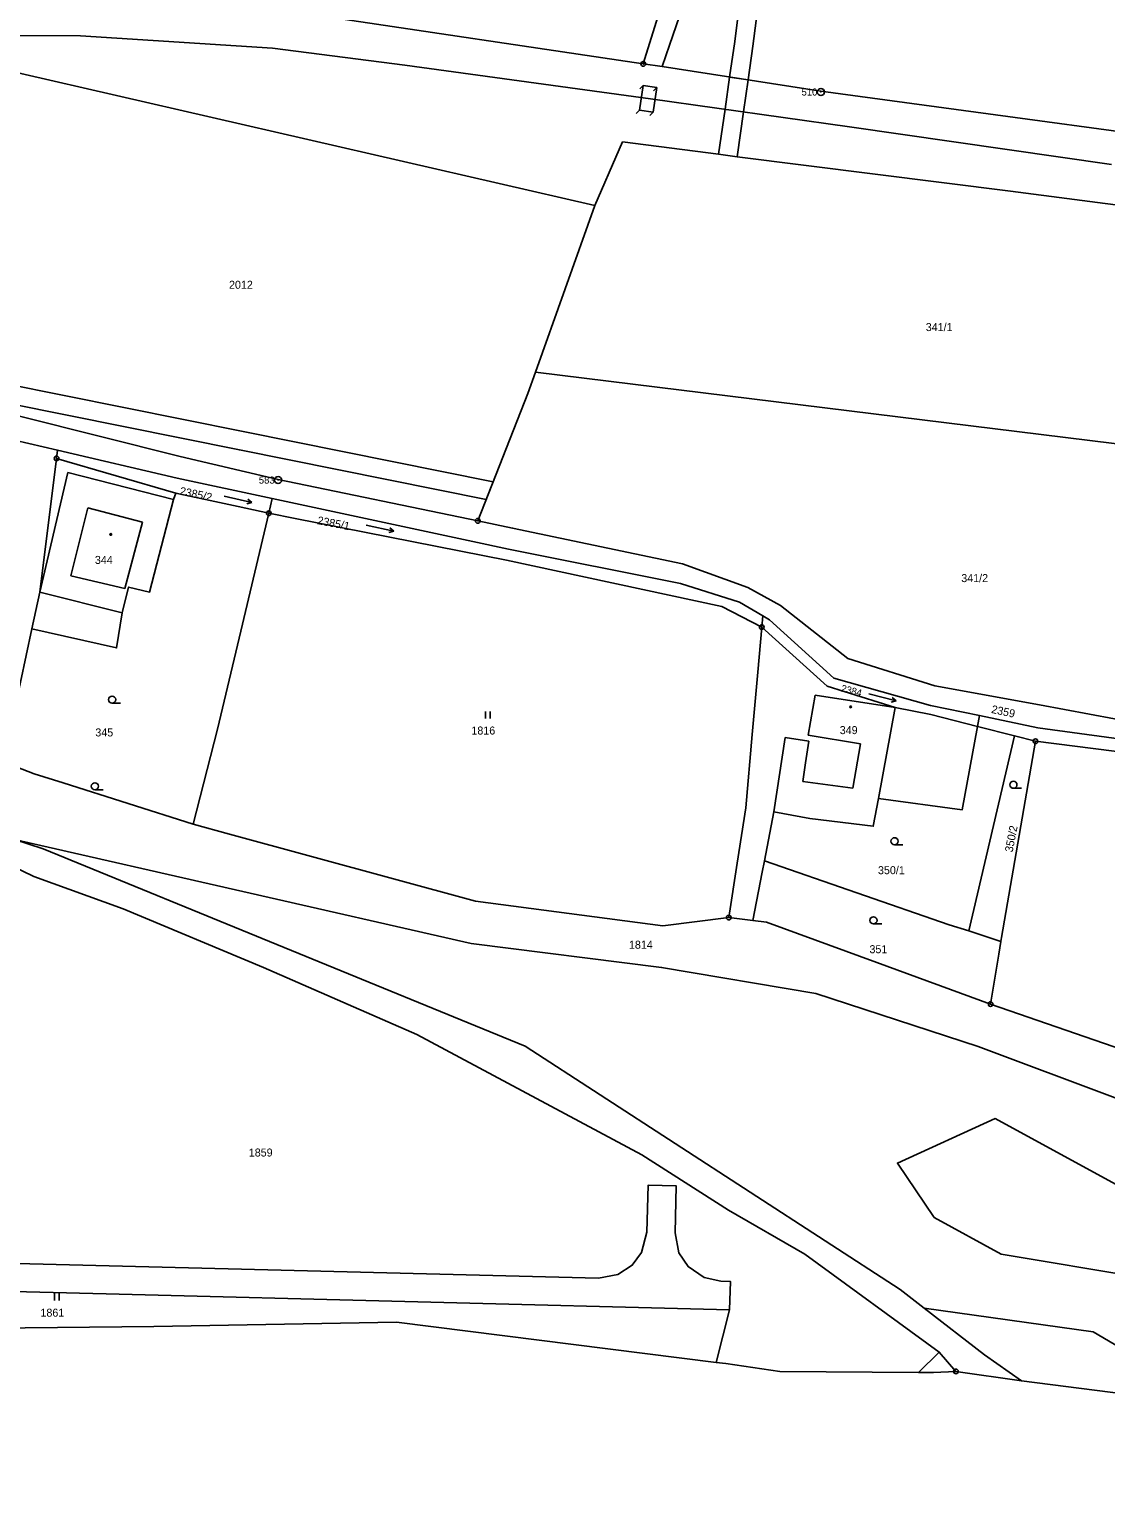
# Model space of a CAD drawing. Extents: x -504988 to -494607, y -1123820 to -1114018.
# Drawn here: x -500871.3 to -500642.7, y -1121663.8 to -1121354.5 of the extents above; entities that cross this region are included whole.
import ezdxf

# ---------------------------------------------------------------- set-up
doc = ezdxf.new("R2010")
doc.units = 0
for name, color, linetype in [('Hranice parcel', 7, 'Continuous'), ('Parcelní čísla', 7, 'Continuous'), ('Polygon ku', 7, 'Continuous'), ('Poz předměty', 7, 'Continuous'), ('Vnitřní kresba', 7, 'Continuous'), ('Věcná břemena k části', 7, 'Continuous'), ('Značky bodu BP', 7, 'Continuous'), ('Značky budov', 7, 'Continuous'), ('Značky kultur', 7, 'Continuous')]:
    doc.layers.add(name, color=color, linetype=linetype)

msp = doc.modelspace()

# ---------------------------------------------------------------- linework, layer by layer
at = {"layer": 'Hranice parcel'}
for p, q in [((-500736.95, -1121362.41), (-500740.93, -1121361.85)), ((-500592.37, -1121398.1), (-500662.99, -1121388.88)), ((-500751.26, -1121391.94), (-500763.83, -1121427.34)), ((-500763.83, -1121427.34), (-500626.53, -1121444.24)), ((-500874.41, -1121441.77), (-500865.27, -1121443.9)), ((-500865.49, -1121445.64), (-500865.27, -1121443.9)), ((-500840.16, -1121452.97), (-500865.49, -1121445.64)), ((-500819.71, -1121454.13), (-500820.45, -1121457.26)), ((-500715.59, -1121479.05), (-500715.8, -1121481.45)), ((-500669.56, -1121500.25), (-500669.98, -1121502.56)), ((-500671.79, -1121545.93), (-500662.11, -1121504.57)), ((-500669.98, -1121502.56), (-500662.11, -1121504.57)), ((-500662.11, -1121504.57), (-500657.68, -1121505.7)), ((-500722.8, -1121543.13), (-500717.66, -1121543.78)), ((-500671.79, -1121545.93), (-500665.04, -1121548.2)), ((-500722.6, -1121626.43), (-500725.45, -1121637.62)), ((-500711.93, -1121639.55), (-500682.48, -1121639.75)), ((-500682.48, -1121639.75), (-500679.35, -1121639.77))]:
    msp.add_line(p, q, dxfattribs=at)
for points in [[(-500690.57, -1121193.22), (-500703.36, -1121227.53), (-500712.38, -1121256.12), (-500723.06, -1121305.36), (-500727.01, -1121333.6), (-500735.38, -1121357.86), (-500736.95, -1121362.41)], [(-500725.11, -1121294.84), (-500727.31, -1121304.65), (-500731.94, -1121332.69), (-500740.93, -1121361.85)], [(-500740.93, -1121361.85), (-500811.39, -1121351.34), (-500852.46, -1121350.08)], [(-500751.26, -1121391.94), (-500873.05, -1121363.84), (-500902.25, -1121362.4), (-500923.9, -1121363.52)], [(-500736.95, -1121362.41), (-500703.27, -1121367.64), (-500597.75, -1121381.92), (-500477.19, -1121398.11), (-500356.62, -1121414.3), (-500315.76, -1121422.98), (-500161.41, -1121474.74), (-500042.51, -1121512.37), (-499891.6, -1121561.19), (-499861.16, -1121571.4), (-499858.09, -1121572.43), (-499855.23, -1121568.88), (-499853.4, -1121569.81), (-499853.07, -1121569.98)], [(-500745.37, -1121378.41), (-500746.07, -1121380.02), (-500751.26, -1121391.94)], [(-500662.99, -1121388.88), (-500720.99, -1121381.55), (-500724.95, -1121380.99), (-500745.37, -1121378.41)], [(-500900.02, -1121427.3), (-500892.26, -1121430.03), (-500873.35, -1121436.67), (-500839.28, -1121445.2), (-500818.48, -1121450.11), (-500776.09, -1121458.88)], [(-500763.83, -1121427.34), (-500765.42, -1121431.83), (-500776.09, -1121458.88)], [(-500865.49, -1121445.64), (-500869.08, -1121474.01), (-500870.74, -1121481.82)], [(-500865.27, -1121443.9), (-500839.89, -1121449.8), (-500819.71, -1121454.13)], [(-500870.74, -1121481.82), (-500852.77, -1121485.86), (-500851.59, -1121478.44), (-500850.2, -1121472.96), (-500845.76, -1121474.01), (-500840.68, -1121454.34), (-500840.16, -1121452.97)], [(-500820.45, -1121457.26), (-500826.92, -1121455.85), (-500840.16, -1121452.97)], [(-500819.71, -1121454.13), (-500777.12, -1121463.27), (-500769.52, -1121464.9), (-500733.07, -1121472.16), (-500720.52, -1121476.15), (-500715.59, -1121479.05)], [(-500836.53, -1121523.32), (-500831.3, -1121503.14), (-500826.38, -1121482.32), (-500825.39, -1121478.13), (-500820.45, -1121457.26)], [(-500715.8, -1121481.45), (-500724.29, -1121477.11), (-500769.95, -1121467.26), (-500814.87, -1121458.36), (-500820.45, -1121457.26)], [(-500776.09, -1121458.88), (-500768.67, -1121460.41), (-500732.61, -1121467.98), (-500718.71, -1121473.02), (-500711.84, -1121476.83), (-500697.53, -1121488.14), (-500679.07, -1121493.94), (-500656.85, -1121497.97), (-500640.87, -1121500.9), (-500631.84, -1121501.01)], [(-500715.59, -1121479.05), (-500714.16, -1121479.89), (-500700.47, -1121492.27), (-500679.94, -1121498.09), (-500669.56, -1121500.25)], [(-500870.74, -1121481.82), (-500875.55, -1121504.45), (-500875.85, -1121508.37), (-500874.09, -1121511.1)], [(-500715.8, -1121481.45), (-500716.64, -1121491.01), (-500717.47, -1121500.37), (-500717.81, -1121504.23), (-500719.18, -1121519.81), (-500721.01, -1121531.58), (-500722.8, -1121543.13)], [(-500669.98, -1121502.56), (-500679.9, -1121500.03), (-500687.45, -1121498.52), (-500701.88, -1121494.02), (-500715.8, -1121481.45)], [(-500585.55, -1121517.36), (-500587.8, -1121513.67), (-500607.61, -1121508.47), (-500617.46, -1121506.84), (-500627.25, -1121505.73), (-500641.03, -1121505.04), (-500657.2, -1121502.82), (-500669.56, -1121500.25)], [(-500669.98, -1121502.56), (-500673.24, -1121520.29), (-500691.02, -1121517.85), (-500692.11, -1121523.75), (-500705.55, -1121522.1), (-500713.24, -1121520.67), (-500715.23, -1121531.09)], [(-500657.68, -1121505.7), (-500664.89, -1121547.36), (-500665.04, -1121548.2)], [(-500585.55, -1121517.36), (-500617.74, -1121510.38), (-500627.3, -1121508.95), (-500641, -1121507.8), (-500657.68, -1121505.7)], [(-500874.09, -1121511.1), (-500870.23, -1121512.61), (-500864.09, -1121514.56), (-500836.53, -1121523.32)], [(-500722.8, -1121543.13), (-500736.77, -1121544.89), (-500776.55, -1121539.63), (-500828.81, -1121525.42), (-500836.53, -1121523.32)], [(-500874.41, -1121526.57), (-500777.49, -1121548.63), (-500737.05, -1121553.73), (-500704.29, -1121559.25), (-500669.82, -1121570.54), (-500611.11, -1121592.54), (-500572.54, -1121605.34), (-500559.62, -1121606.59), (-500553.26, -1121605.17), (-500533.2, -1121604.53), (-500509.38, -1121604.76), (-500480.9, -1121603.04), (-500474.44, -1121603.7)], [(-500874.41, -1121526.57), (-500868.34, -1121528.51), (-500766.02, -1121570.45), (-500686.39, -1121622.16), (-500681.34, -1121626.07)], [(-500682.48, -1121639.75), (-500678.12, -1121635.45), (-500706.61, -1121614.66), (-500722.83, -1121605.3), (-500741.28, -1121593.54), (-500789.04, -1121568.01), (-500821.54, -1121553.77), (-500851.38, -1121541.32), (-500870.35, -1121534.44), (-500875.3, -1121532), (-500878.74, -1121531.16), (-500880.51, -1121532.35)], [(-500717.66, -1121543.78), (-500715.7, -1121533.48), (-500715.23, -1121531.09)], [(-500715.23, -1121531.09), (-500676.01, -1121544.69), (-500671.79, -1121545.93)], [(-500667.21, -1121561.51), (-500691.35, -1121552.65), (-500714.77, -1121544.15), (-500717.66, -1121543.78)], [(-500665.04, -1121548.2), (-500665.48, -1121550.9), (-500667.21, -1121561.51)], [(-500472.98, -1121588.34), (-500480.26, -1121592.21), (-500492.56, -1121594.8), (-500533.66, -1121596.03), (-500553.37, -1121596.25), (-500571.08, -1121594.77), (-500667.21, -1121561.51)], [(-500681.34, -1121626.07), (-500645.4, -1121631.11), (-500627.77, -1121641.56), (-500600.14, -1121648.61), (-500575.22, -1121652.3), (-500635.34, -1121619.61), (-500664.97, -1121614.6), (-500679.19, -1121606.84), (-500686.99, -1121595.27), (-500666.26, -1121585.83), (-500573.75, -1121636.27), (-500550.8, -1121631.78)], [(-500907.77, -1121615.74), (-500750.43, -1121619.72), (-500746.35, -1121618.97), (-500743.29, -1121616.98), (-500741.29, -1121614.31), (-500740.18, -1121609.98), (-500739.93, -1121599.98), (-500733.93, -1121600.14), (-500734.19, -1121610.13), (-500733.36, -1121614.38), (-500731.44, -1121617.28), (-500728.03, -1121619.62), (-500724.44, -1121620.38), (-500722.44, -1121620.43), (-500722.6, -1121626.43)], [(-500722.6, -1121626.43), (-500854.98, -1121623.08), (-500987.36, -1121619.73), (-500992.12, -1121619.5), (-500997.62, -1121618.94), (-501002.66, -1121618.18), (-501008.42, -1121617), (-501056.44, -1121605.66)], [(-500681.34, -1121626.07), (-500668.53, -1121635.98), (-500660.64, -1121641.55)], [(-501062.38, -1121630.82), (-501029.59, -1121640.34), (-501010.64, -1121641.56), (-500959.5, -1121634.57), (-500892.72, -1121630.46), (-500844.84, -1121629.97), (-500793.35, -1121629.08), (-500725.45, -1121637.62)], [(-500725.45, -1121637.62), (-500723.44, -1121637.87), (-500711.93, -1121639.55)], [(-500679.35, -1121639.77), (-500674.56, -1121639.53), (-500660.64, -1121641.55)], [(-500660.64, -1121641.55), (-500622.96, -1121646.37), (-500587.41, -1121659.3), (-500553.81, -1121663.84)]]:
    msp.add_lwpolyline(points, dxfattribs=at)
at = {"layer": 'Polygon ku'}
msp.add_lwpolyline([(-501111.6, -1121612.08), (-501062.38, -1121630.82), (-501029.59, -1121640.34), (-501010.64, -1121641.56), (-500959.5, -1121634.57), (-500892.72, -1121630.46), (-500844.84, -1121629.97), (-500793.35, -1121629.08), (-500725.45, -1121637.62), (-500723.44, -1121637.87), (-500711.93, -1121639.55), (-500682.48, -1121639.75), (-500679.35, -1121639.77), (-500674.56, -1121639.53), (-500660.64, -1121641.55), (-500622.96, -1121646.37)], dxfattribs=at)
at = {"layer": 'Poz předměty'}
for p, q in [((-500894.52, -1121355.78), (-500860.42, -1121355.86)), ((-500860.42, -1121355.86), (-500819.69, -1121358.49)), ((-500819.69, -1121358.49), (-500791.58, -1121362.09)), ((-500791.58, -1121362.09), (-500739.43, -1121369.22)), ((-500739.43, -1121369.22), (-500697.19, -1121375.2)), ((-500697.19, -1121375.2), (-500641.54, -1121383.23))]:
    msp.add_line(p, q, dxfattribs=at)
at = {"layer": 'Vnitřní kresba'}
for p, q in [((-500740.99, -1121366.42), (-500741.77, -1121371.69)), ((-500741.7, -1121367.13), (-500740.99, -1121366.42)), ((-500740.99, -1121366.42), (-500738.06, -1121366.87)), ((-500738.06, -1121366.87), (-500738.87, -1121372.1)), ((-500738.77, -1121367.58), (-500738.06, -1121366.87)), ((-500742.48, -1121372.4), (-500741.77, -1121371.69)), ((-500741.77, -1121371.69), (-500738.87, -1121372.1)), ((-500739.58, -1121372.81), (-500738.87, -1121372.1)), ((-500869.08, -1121474.01), (-500863.13, -1121448.65)), ((-500863.13, -1121448.65), (-500840.68, -1121454.34)), ((-500862.48, -1121470.55), (-500858.84, -1121456.1)), ((-500858.84, -1121456.1), (-500847.23, -1121459.14)), ((-500847.23, -1121459.14), (-500851.01, -1121473.24)), ((-500851.01, -1121473.24), (-500862.48, -1121470.55)), ((-500851.59, -1121478.44), (-500869.08, -1121474.01)), ((-500705.9, -1121504.4), (-500704.45, -1121495.91)), ((-500704.45, -1121495.91), (-500687.45, -1121498.52)), ((-500687.45, -1121498.52), (-500691.02, -1121517.85)), ((-500694.84, -1121506.21), (-500705.9, -1121504.4)), ((-500713.24, -1121520.67), (-500710.84, -1121504.89)), ((-500710.84, -1121504.89), (-500705.8, -1121505.66)), ((-500705.8, -1121505.66), (-500706.5, -1121510.25)), ((-500696.43, -1121515.65), (-500694.84, -1121506.21)), ((-500706.5, -1121510.25), (-500707.1, -1121514.21)), ((-500707.1, -1121514.21), (-500696.43, -1121515.65))]:
    msp.add_line(p, q, dxfattribs=at)
at = {"layer": 'Věcná břemena k části'}
for points in [[(-500721.51, -1121357.05), (-500722.6, -1121364.64), (-500718.69, -1121365.25), (-500717.68, -1121358.06), (-500716.03, -1121345.47), (-500712.09, -1121315.21), (-500711.18, -1121310.28), (-500710.13, -1121305.55), (-500700.38, -1121273.68), (-500684.33, -1121221.21), (-500676.39, -1121195.5), (-500680.38, -1121194.86), (-500688.16, -1121220.05), (-500704.21, -1121272.51), (-500713.98, -1121304.46), (-500715.1, -1121309.49), (-500716.05, -1121314.64), (-500720, -1121344.97)], [(-500723.58, -1121371.46), (-500724.95, -1121380.99), (-500720.99, -1121381.55), (-500719.65, -1121372.02), (-500718.69, -1121365.25), (-500722.6, -1121364.64)], [(-500825.88, -1121439.91), (-500876.58, -1121429.69), (-500878.79, -1121430.84), (-500879.81, -1121434.4), (-500876.03, -1121435.73), (-500875.53, -1121433.98), (-500826.67, -1121443.83), (-500774.31, -1121454.37), (-500772.82, -1121450.59)], [(-500682.48, -1121639.75), (-500679.35, -1121639.77), (-500674.56, -1121639.53), (-500678.12, -1121635.45)]]:
    msp.add_lwpolyline(points, close=True, dxfattribs=at)
at = {"layer": 'Značky bodu BP'}
for centre, radius in [((-500740.93, -1121361.85), 0.5), ((-500740.93, -1121361.85), 0.0303), ((-500703.24, -1121367.8), 0.75), ((-500703.24, -1121367.8), 0.03), ((-500865.49, -1121445.64), 0.5), ((-500865.49, -1121445.64), 0.0303), ((-500818.46, -1121450.22), 0.75), ((-500818.46, -1121450.22), 0.03), ((-500820.45, -1121457.26), 0.5), ((-500820.45, -1121457.26), 0.0303), ((-500776.09, -1121458.88), 0.5), ((-500776.09, -1121458.88), 0.0303), ((-500715.8, -1121481.45), 0.5), ((-500715.8, -1121481.45), 0.0303), ((-500657.68, -1121505.7), 0.5), ((-500657.68, -1121505.7), 0.0303), ((-500722.8, -1121543.13), 0.5), ((-500722.8, -1121543.13), 0.0303), ((-500667.21, -1121561.51), 0.5), ((-500667.21, -1121561.51), 0.0303), ((-500674.56, -1121639.53), 0.5), ((-500674.56, -1121639.53), 0.0303)]:
    msp.add_circle(centre, radius, dxfattribs=at)
at = {"layer": 'Značky budov'}
for centre in [(-500853.98, -1121461.78), (-500696.91, -1121498.4)]:
    msp.add_circle(centre, 0.175, dxfattribs=at)
at = {"layer": 'Značky kultur'}
for p, q in [((-500829.91, -1121453.67), (-500824.06, -1121455.02)), ((-500824.06, -1121455.02), (-500825.13, -1121455.29)), ((-500824.06, -1121455.02), (-500824.9, -1121454.31)), ((-500799.76, -1121459.81), (-500793.89, -1121461.06)), ((-500793.89, -1121461.06), (-500794.95, -1121461.34)), ((-500793.89, -1121461.06), (-500794.74, -1121460.36)), ((-500853.7, -1121497.61), (-500851.95, -1121497.61)), ((-500693.06, -1121495.59), (-500687.27, -1121497.14)), ((-500687.27, -1121497.14), (-500688.34, -1121497.37)), ((-500687.27, -1121497.14), (-500688.08, -1121496.4)), ((-500774.43, -1121500.85), (-500774.43, -1121499.35)), ((-500773.43, -1121500.85), (-500773.43, -1121499.35)), ((-500857.37, -1121516.01), (-500855.62, -1121516.01)), ((-500662.36, -1121515.69), (-500660.61, -1121515.69)), ((-500687.6, -1121527.68), (-500685.85, -1121527.68)), ((-500692.07, -1121544.48), (-500690.32, -1121544.48)), ((-500865.92, -1121624.49), (-500865.92, -1121622.99)), ((-500864.92, -1121624.49), (-500864.92, -1121622.99))]:
    msp.add_line(p, q, dxfattribs=at)
for centre in [(-500853.7, -1121496.86), (-500857.37, -1121515.26), (-500662.36, -1121514.94), (-500687.6, -1121526.93), (-500692.07, -1121543.73)]:
    msp.add_circle(centre, 0.75, dxfattribs=at)

# ---------------------------------------------------------------- texts
at = {"layer": 'Parcelní čísla'}
for s, p in [('2012', (-500828.89, -1121409.59)), ('341/1', (-500680.97, -1121418.58)), ('344', (-500857.36, -1121468.03)), ('341/2', (-500673.43, -1121471.89)), ('345', (-500857.27, -1121504.67)), ('1816', (-500777.43, -1121504.27)), ('349', (-500699.23, -1121504.18)), ('350/1', (-500691.11, -1121533.93)), ('1814', (-500743.98, -1121549.76)), ('351', (-500692.92, -1121550.71)), ('1859', (-500824.69, -1121593.89)), ('1861', (-500868.92, -1121627.91))]:
    msp.add_text(s, height=1.7, dxfattribs=at).set_placement(p)
for s, height, rotation, p in [('2385/2', 1.7, 348, (-500839.48, -1121453.31)), ('2385/1', 1.7, 349, (-500810.25, -1121459.56)), ('2384', 1.5, 345, (-500699.08, -1121495.09)), ('2359', 1.7, 348, (-500667.16, -1121499.66)), ('350/2', 1.7, 79, (-500662.54, -1121529.36))]:
    msp.add_text(s, height=height, rotation=rotation, dxfattribs=at).set_placement(p)
at = {"layer": 'Značky bodu BP'}
for s, p in [('510', (-500707.34, -1121368.55)), ('583', (-500822.56, -1121450.97))]:
    msp.add_text(s, height=1.5, dxfattribs=at).set_placement(p)

doc.saveas('drawing.dxf')
